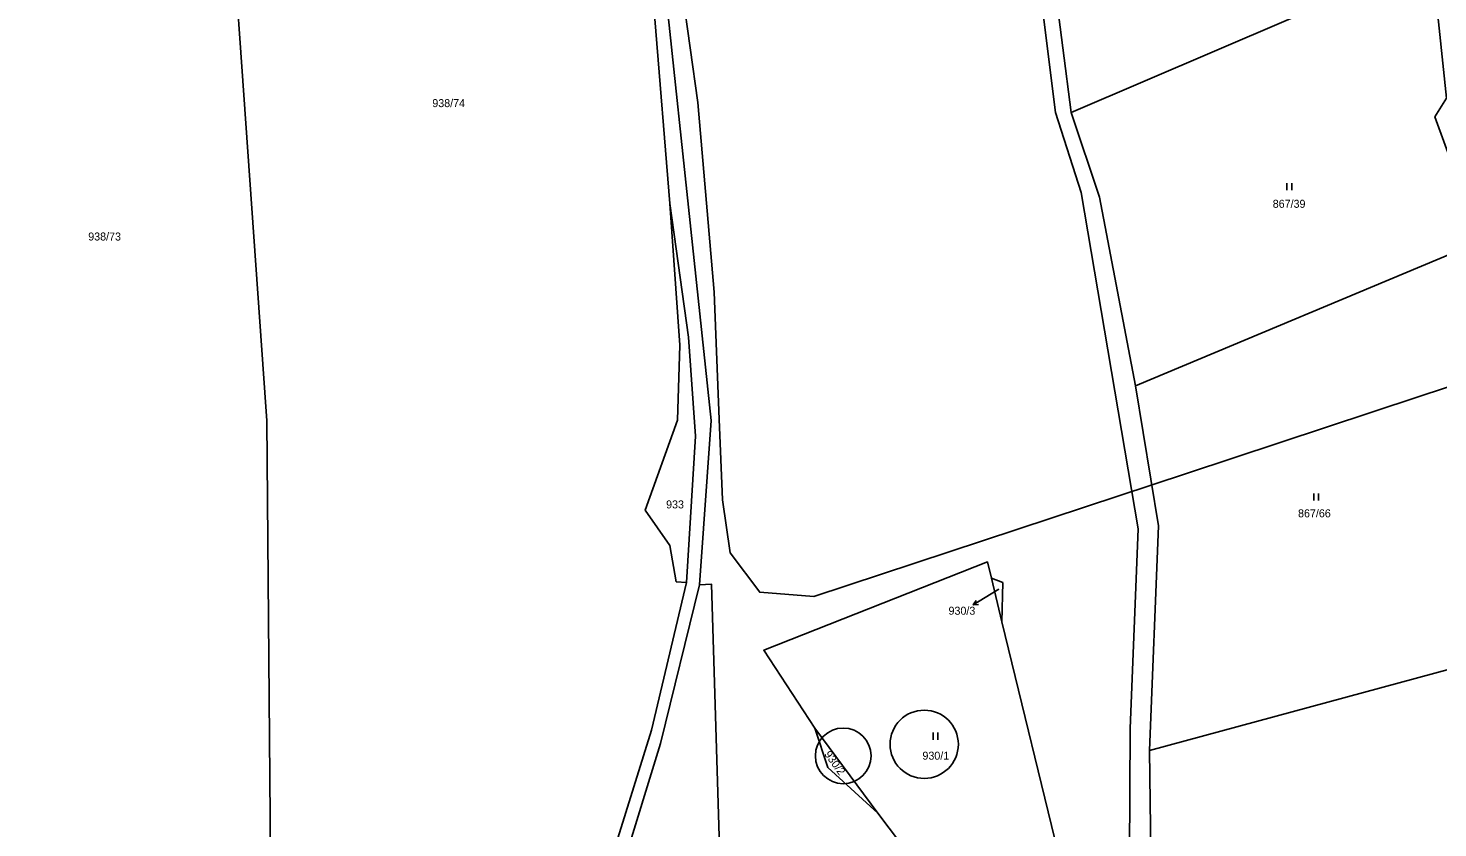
# Model space of a CAD drawing. Extents: x -588699 to -585793, y -1060280 to -1056731.
# Drawn here: x -588120.4 to -587820.9, y -1057977.7 to -1057807.9 of the extents above; entities that cross this region are included whole.
import ezdxf

# ---------------------------------------------------------------- set-up
doc = ezdxf.new("R2010")
doc.units = 0
for name, color, linetype in [('Druh pozemku', 7, 'Continuous'), ('Parcela nároku', 7, 'Continuous'), ('Parcelní číslo', 7, 'Continuous'), ('Vnitřní obvod', 7, 'Continuous'), ('Změna katastrální hranice', 7, 'Continuous')]:
    doc.layers.add(name, color=color, linetype=linetype)

msp = doc.modelspace()

# ---------------------------------------------------------------- linework, layer by layer
at = {"layer": 'Druh pozemku'}
for p, q in [((-587852.99, -1057840.78), (-587852.99, -1057842.28)), ((-587851.96, -1057842.28), (-587851.96, -1057840.78)), ((-587847.29, -1057906.65), (-587847.29, -1057908.15)), ((-587846.27, -1057908.15), (-587846.27, -1057906.65)), ((-587928.16, -1057957.47), (-587928.16, -1057958.97)), ((-587927.14, -1057958.97), (-587927.14, -1057957.47))]:
    msp.add_line(p, q, dxfattribs=at)
at = {"layer": 'Parcela nároku'}
for points in [[(-587998.57, -1057617.58), (-587998.64, -1057610.93), (-588083.68, -1057635.65), (-588081.67, -1057721.71), (-588069.75, -1057891.27), (-588068.25, -1058068.03), (-588067.88, -1058079.03), (-588018.76, -1058070.8), (-588007.76, -1058020.32), (-587988.03, -1057956.92), (-587980.59, -1057925.6), (-587982.76, -1057925.42), (-587984.09, -1057917.75), (-587989.35, -1057910.25), (-587982.46, -1057891.11), (-587981.97, -1057875.19), (-587984.13, -1057845.06), (-587987.3, -1057805.85), (-587992.29, -1057757.6), (-587992.48, -1057712.96)], [(-588146.85, -1057654), (-588083.68, -1057635.65), (-588081.67, -1057721.71), (-588069.75, -1057891.27), (-588068.25, -1058068.03), (-588129.14, -1058075.51), (-588132.27, -1058023.47), (-588130.87, -1057996.67), (-588127.55, -1057944.29), (-588127.1, -1057903.81), (-588141.26, -1057786.74), (-588142.09, -1057762.75), (-588146.38, -1057724.97)], [(-587894.16, -1057718.6), (-587831.02, -1057693.37), (-587822.22, -1057792.91), (-587898.85, -1057825.76), (-587902.37, -1057798.19), (-587895.72, -1057745.19)], [(-587817.19, -1057838.74), (-587821.55, -1057826.67), (-587819.09, -1057822.75), (-587822.22, -1057792.91), (-587898.85, -1057825.76), (-587892.79, -1057843.76), (-587885.17, -1057883.85), (-587814.43, -1057854.23)], [(-587798.19, -1057867.45), (-587810.86, -1057828.46), (-587819.09, -1057822.75), (-587821.55, -1057826.67), (-587817.19, -1057838.74), (-587814.43, -1057854.23), (-587813.86, -1057867.36)], [(-587980.15, -1057873.46), (-587978.66, -1057894.49), (-587980.59, -1057925.6), (-587982.76, -1057925.42), (-587984.09, -1057917.75), (-587989.35, -1057910.25), (-587982.46, -1057891.11), (-587981.97, -1057875.19), (-587984.13, -1057845.06)], [(-587814.02, -1057942.82), (-587814.18, -1057923.16), (-587813.75, -1057915.55), (-587812.08, -1057885.63), (-587813.86, -1057867.36), (-587814.43, -1057854.23), (-587885.17, -1057883.85), (-587880.28, -1057913.57), (-587882.18, -1057961.3)], [(-587913.54, -1057933.95), (-587900.93, -1057985.93), (-587911.91, -1058005.56), (-587913.87, -1058009.06), (-587939.9, -1057974.61), (-587953.32, -1057956.49), (-587964.15, -1057939.99), (-587916.62, -1057921.23), (-587915.79, -1057924.66)], [(-587986.08, -1057959.78), (-588001.51, -1058009.97), (-588006.28, -1058029.92), (-587972.09, -1058030.78), (-587975.24, -1057925.95), (-587977.79, -1057926.08)], [(-587913.38, -1057925.6), (-587915.79, -1057924.66), (-587913.54, -1057933.95)], [(-587787.01, -1057976), (-587780.16, -1057998.87), (-587781.12, -1058000.9), (-587778.11, -1058005.58), (-587765.81, -1058045.87), (-587784.84, -1058048.59), (-587789.52, -1058033.22), (-587813.41, -1058035.08), (-587812.97, -1058031.76), (-587869.58, -1058044.93), (-587875.83, -1058033.11), (-587877.91, -1058017.26), (-587868.98, -1058016.13), (-587870.56, -1058004.56), (-587879.42, -1058005.73), (-587880.07, -1058001.83), (-587880.42, -1057997.53), (-587880.67, -1057994.5), (-587881.93, -1057982.97), (-587882.18, -1057961.3), (-587814.02, -1057942.82), (-587813.68, -1057985.91), (-587810.98, -1057985.75), (-587805.91, -1057973.34)], [(-587953.32, -1057956.49), (-587939.9, -1057974.61), (-587950.57, -1057964.9)]]:
    msp.add_lwpolyline(points, close=True, dxfattribs=at)
for points in [[(-587989.27, -1057759.84), (-587975.36, -1057891.18), (-587977.79, -1057926.08), (-587986.08, -1057959.78), (-588001.51, -1058009.97), (-588006.28, -1058029.92), (-588007.49, -1058035), (-588008.85, -1058040.67), (-588013.12, -1058060.06), (-588012.85, -1058086.07), (-588008.73, -1058107.2), (-588003.37, -1058114.43), (-588008.77, -1058113.8), (-588014.59, -1058105.87), (-588019.99, -1058095.55), (-588026.59, -1058082.94), (-588018.76, -1058070.8), (-588007.76, -1058020.32), (-587988.03, -1057956.92), (-587980.59, -1057925.6), (-587978.66, -1057894.49), (-587980.15, -1057873.46), (-587984.13, -1057845.06), (-587987.3, -1057805.85)], [(-587989.27, -1057759.84), (-587975.36, -1057891.18), (-587977.79, -1057926.08), (-587975.24, -1057925.95), (-587972.09, -1058030.78)], [(-587902.37, -1057798.19), (-587898.85, -1057825.76), (-587892.79, -1057843.76), (-587885.17, -1057883.85), (-587880.28, -1057913.57), (-587882.18, -1057961.3), (-587881.93, -1057982.97), (-587880.67, -1057994.5), (-587880.42, -1057997.53), (-587884.5, -1057994.99), (-587886.46, -1057983.33), (-587886.34, -1057956.6), (-587884.58, -1057914.16), (-587896.7, -1057842.78), (-587902.17, -1057825.76), (-587905.69, -1057797.41)], [(-587886.46, -1057983.33), (-587886.34, -1057956.6), (-587884.58, -1057914.16), (-587896.7, -1057842.78), (-587902.17, -1057825.76), (-587905.69, -1057797.41)], [(-587913.87, -1058009.06), (-587939.9, -1057974.61), (-587950.57, -1057964.9), (-587953.32, -1057956.49), (-587964.15, -1057939.99), (-587916.62, -1057921.23), (-587915.79, -1057924.66), (-587913.38, -1057925.6), (-587913.54, -1057933.95), (-587900.93, -1057985.93)]]:
    msp.add_lwpolyline(points, dxfattribs=at)
at = {"layer": 'Parcelní číslo'}
for p, q in [((-587914.2, -1057927.01), (-587917.09, -1057928.77)), ((-587917.09, -1057928.77), (-587919.65, -1057930.33))]:
    msp.add_line(p, q, dxfattribs=at)
msp.add_lwpolyline([(-587918.54, -1057930.24), (-587919.65, -1057930.33), (-587919.06, -1057929.38)], dxfattribs=at)
at = {"layer": 'Vnitřní obvod'}
msp.add_lwpolyline([(-587984.69, -1057777.13), (-587978.14, -1057823.66), (-587974.7, -1057863.91), (-587973.63, -1057890.93), (-587972.95, -1057908.02), (-587971.26, -1057919.27), (-587964.99, -1057927.66), (-587953.51, -1057928.55), (-587874.36, -1057902.42), (-587824.94, -1057886.11), (-587808.77, -1057880.77), (-587790.89, -1057881.51), (-587772.08, -1057887.36), (-587760.97, -1057897.48), (-587755.82, -1057909.27)], dxfattribs=at)
at = {"layer": 'Změna katastrální hranice'}
for centre, radius in [((-587930.06, -1057959.95), 7.25), ((-587947.27, -1057962.41), 5.91)]:
    msp.add_circle(centre, radius, dxfattribs=at)

# ---------------------------------------------------------------- texts
at = {"layer": 'Parcela nároku'}
for s, height, p in [('938/74', 1.7, (-588034.57, -1057824.62)), ('867/39', 1.7, (-587856.02, -1057846)), ('938/73', 1.7, (-588107.67, -1057852.95)), ('933', 1.7, (-587984.9, -1057909.85)), ('867/66', 1.7, (-587850.64, -1057911.74)), ('930/3', 0.1, (-587914.39, -1057927.01)), ('930/1', 1.7, (-587930.44, -1057963.22))]:
    msp.add_text(s, height=height, dxfattribs=at).set_placement(p)
msp.add_text('930/2', height=1.7, rotation=305.8282, dxfattribs=at).set_placement((-587951.39, -1057962.07))
at = {"layer": 'Parcelní číslo'}
msp.add_text('930/3', height=1.7, dxfattribs=at).set_placement((-587924.9, -1057932.43))

doc.saveas('drawing.dxf')
